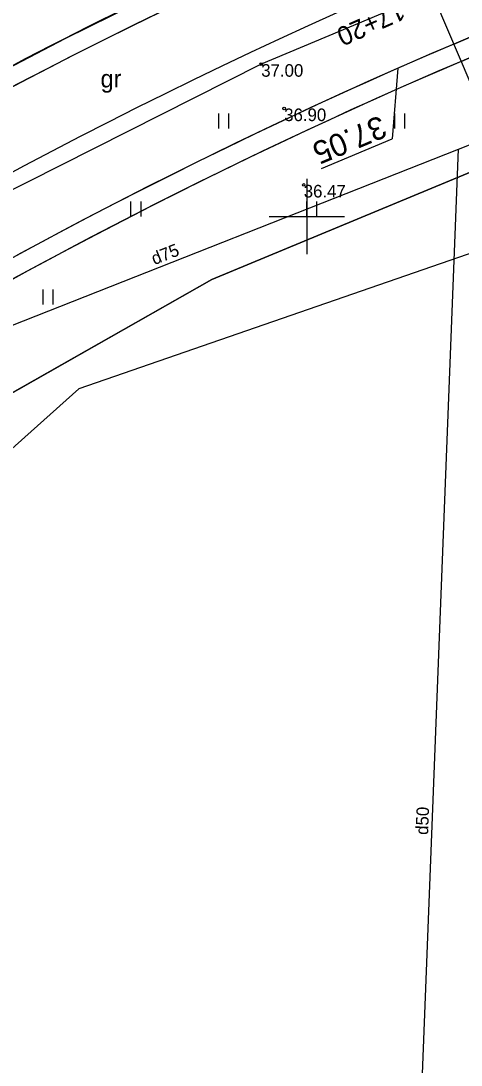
# Model space of a CAD drawing. Extents: x 469981 to 472086, y 246785 to 247785.
# Drawn here: x 470388.62 to 470406.14, y 247066.25 to 247107.78 of the extents above; entities that cross this region are included whole.
import ezdxf

# ---------------------------------------------------------------- set-up
doc = ezdxf.new("R2010")
doc.units = 0
for name, color, linetype in [('0_922', 7, 'Continuous'), ('0_Asfalta_mala', 7, 'Continuous'), ('0_Asfalta_Nomale', 7, 'Continuous'), ('0_Ruut_Braukt', 7, 'Continuous'), ('0_Ruut_nomale', 7, 'Continuous'), ('0_Ruutojums_Nobrauktuves_pieslegumi', 7, 'Continuous'), ('0_vertikals', 7, 'Continuous'), ('0_vertkals_cipari', 7, 'Continuous'), ('21', 7, 'Continuous'), ('5_patagas', 7, 'Continuous'), ('6_piketaza', 7, 'Continuous'), ('CELI_CMAL_####_####_#', 7, 'Continuous'), ('CELI_CSEG_####_TKST_#', 7, 'Continuous'), ('DREN_VADP_####_####_#', 7, 'Continuous'), ('DREN_VADP_####_TKST_#', 7, 'Continuous'), ('DREN_VADP_KLKT_####_#', 7, 'Continuous'), ('DREN_VADP_KLKT_TKST_#', 7, 'Continuous'), ('GEOD_ELEM_####_####_#', 7, 'Continuous'), ('RAMI_UZMR_####_####_#', 7, 'Continuous'), ('RELJ_AATZ_####_TKST_#', 7, 'Continuous'), ('RELJ_ELEM_####_####_#', 7, 'Continuous'), ('ROBZ_IERR_####_####_#', 7, 'Continuous'), ('ROBZ_PROJ_####_####_#', 7, 'Continuous'), ('TERT_ELEM_####_####_#', 7, 'Continuous')]:
    doc.layers.add(name, color=color, linetype=linetype)

msp = doc.modelspace()

# ---------------------------------------------------------------- linework, layer by layer
at = {"layer": '0_922'}
msp.add_arc((470487.184, 246916.514), 210, 113.13829, 135.11501, dxfattribs=at)
at = {"layer": '0_Asfalta_mala'}
msp.add_line((470426.43, 247115.66), (470405.843, 247106.863), dxfattribs=at)
for radius in [213, 207]:
    msp.add_arc((470487.184, 246916.514), radius, 113.13829, 135.11501, dxfattribs=at)
at = {"layer": '0_Asfalta_Nomale'}
msp.add_line((470426.725, 247114.971), (470406.138, 247106.173), dxfattribs=at)
msp.add_arc((470487.184, 246916.514), 206.25, 113.13829, 135.11501, dxfattribs=at)
at = {"layer": '0_Ruut_Braukt'}
msp.add_line((470405.843, 247106.863), (470426.43, 247115.66), dxfattribs=at)
for radius in [213, 207]:
    msp.add_arc((470487.184, 246916.514), radius, 113.13829, 135.11501, dxfattribs=at)
at = {"layer": '0_Ruut_nomale'}
for p, q in [((470426.43, 247115.66), (470405.843, 247106.863)), ((470406.138, 247106.173), (470426.725, 247114.971))]:
    msp.add_line(p, q, dxfattribs=at)
msp.add_lwpolyline([(470395.782, 247109.736), (470393.165, 247108.452), (470390.364, 247107.068), (470388.366, 247106.021), (470386.256, 247104.895)], dxfattribs=at)
for radius, end in [(213, 129.44229), (207, 130.0782), (206.25, 130.16049)]:
    msp.add_arc((470487.184, 246916.514), radius, 113.13829, end, dxfattribs=at)
at = {"layer": '0_Ruutojums_Nobrauktuves_pieslegumi'}
msp.add_arc((470487.184, 246916.514), 213.75, 115.31612, 120.08211, dxfattribs=at)
at = {"layer": '0_vertikals'}
for p in [(470403.62, 247105.897), (470400.586, 247101.911)]:
    msp.add_line(p, (470403.396, 247103.087), dxfattribs=at)
at = {"layer": '21'}
msp.add_arc((470487.184, 246916.514), 210, 113.13829, 135.11501, dxfattribs=at)
at = {"layer": '5_patagas'}
msp.add_lwpolyline([(470404.664, 247109.622), (470412.523, 247091.23)], dxfattribs=at)
at = {"layer": 'CELI_CMAL_####_####_#'}
msp.add_lwpolyline([(470440.723, 247107.99), (470440.084, 247118.844), (470439.302, 247119.794), (470438.459, 247120.205), (470437.434, 247120.771), (470435.683, 247121.111), (470417.849, 247114.314), (470398.184, 247106.061), (470376.912, 247095.329), (470368.488, 247089.418), (470350.85, 247073.72), (470334.429, 247056.212), (470317.045, 247039.09), (470299.359, 247021.199), (470279.758, 247002.025), (470265.741, 246988.964), (470242.76, 246971.543), (470223.686, 246958.587), (470209.766, 246949.279)], dxfattribs=at)
at = {"layer": 'DREN_VADP_####_####_#'}
msp.add_lwpolyline([(470404.469, 247062.496), (470406.04, 247102.681)], dxfattribs=at)
at = {"layer": 'DREN_VADP_KLKT_####_#'}
msp.add_lwpolyline([(470374.125, 247090.092), (470375.261, 247090.541), (470388.222, 247095.652), (470406.04, 247102.681), (470426.281, 247110.664)], dxfattribs=at)
at = {"layer": 'GEOD_ELEM_####_####_#'}
for p, q in [((470400, 247101.5), (470400, 247100)), ((470398.5, 247100), (470400, 247100)), ((470400, 247100), (470400, 247098.5)), ((470400, 247100), (470401.5, 247100))]:
    msp.add_line(p, q, dxfattribs=at)
at = {"layer": 'RAMI_UZMR_####_####_#'}
msp.add_lwpolyline([(470682.857, 247179.693), (470601.924, 247155.957), (470538.749, 247139.954), (470448.7, 247112.965), (470443.256, 247108.572), (470439.042, 247107.166), (470426.399, 247105.409), (470390.93, 247093.141), (470379.516, 247082.95), (470369.859, 247080.841), (470357.567, 247068.014), (470285.914, 246993.254), (470269.057, 246978.845), (470246.406, 246963.908), (470178.978, 246918.441), (470154.395, 246901.045), (470104.604, 246871.942), (470081.833, 246858.073)], dxfattribs=at)
at = {"layer": 'RELJ_ELEM_####_####_#'}
for centre in [(470398.184, 247106.061), (470399.097, 247104.296), (470399.875, 247101.259)]:
    msp.add_circle(centre, 0.05, dxfattribs=at)
at = {"layer": 'ROBZ_IERR_####_####_#'}
msp.add_lwpolyline([(470310.127, 246974.356), (470275.956, 246992.729), (470371.503, 247083.47), (470396.219, 247097.502), (470431.624, 247112.202), (470468.364, 247124.23), (470636.973, 247175.147), (470640.03, 247134.708)], dxfattribs=at)
at = {"layer": 'ROBZ_PROJ_####_####_#'}
msp.add_lwpolyline([(471398.351, 247372.094), (471346.741, 247338.478), (471133.176, 247205.05), (471108.425, 247194.786), (471087.339, 247189.709), (471023.306, 247181.157), (470962.604, 247185.245), (470905.63, 247205.857), (470878.75, 247214.454), (470852.344, 247217.039), (470815.743, 247215.147), (470778.583, 247209.26), (470718.669, 247194.633), (470636.973, 247175.147), (470468.364, 247124.23), (470431.624, 247112.202), (470396.219, 247097.502), (470371.503, 247083.47), (470275.956, 246992.729), (470152.342, 246907.761), (470066.737, 246851.23)], dxfattribs=at)
at = {"layer": 'TERT_ELEM_####_####_#'}
for p, q in [((470396.5, 247103.5), (470396.5, 247104.1)), ((470396.9, 247103.5), (470396.9, 247104.1)), ((470403.5, 247103.5), (470403.5, 247104.1)), ((470403.9, 247103.5), (470403.9, 247104.1)), ((470393, 247100), (470393, 247100.6)), ((470393.4, 247100), (470393.4, 247100.6)), ((470400, 247100), (470400, 247100.6)), ((470400.4, 247100), (470400.4, 247100.6)), ((470389.5, 247096.5), (470389.5, 247097.1)), ((470389.9, 247096.5), (470389.9, 247097.1))]:
    msp.add_line(p, q, dxfattribs=at)

# ---------------------------------------------------------------- texts
at = {"layer": '0_vertkals_cipari'}
msp.add_text('37.05', height=0.9, rotation=202.7111, dxfattribs=at).set_placement((470402.92, 247104.043))
at = {"layer": '6_piketaza'}
msp.add_text('17+20', height=0.75, rotation=203.8092, dxfattribs=at).set_placement((470403.694, 247108.581))
at = {"layer": 'CELI_CSEG_####_TKST_#'}
msp.add_text('gr', height=0.7, dxfattribs=at).set_placement((470391.79, 247105.133))
at = {"layer": 'DREN_VADP_####_TKST_#'}
msp.add_text('d50', height=0.5, rotation=87.761, dxfattribs=at).set_placement((470404.823, 247075.397))
at = {"layer": 'DREN_VADP_KLKT_TKST_#'}
msp.add_text('d75', height=0.5, rotation=21.5259, dxfattribs=at).set_placement((470393.931, 247098.066))
at = {"layer": 'RELJ_AATZ_####_TKST_#'}
for s, p in [('37.00', (470398.184, 247105.561)), ('36.90', (470399.097, 247103.796)), ('36.47', (470399.875, 247100.759))]:
    msp.add_text(s, height=0.5, dxfattribs=at).set_placement(p)

doc.saveas('drawing.dxf')
